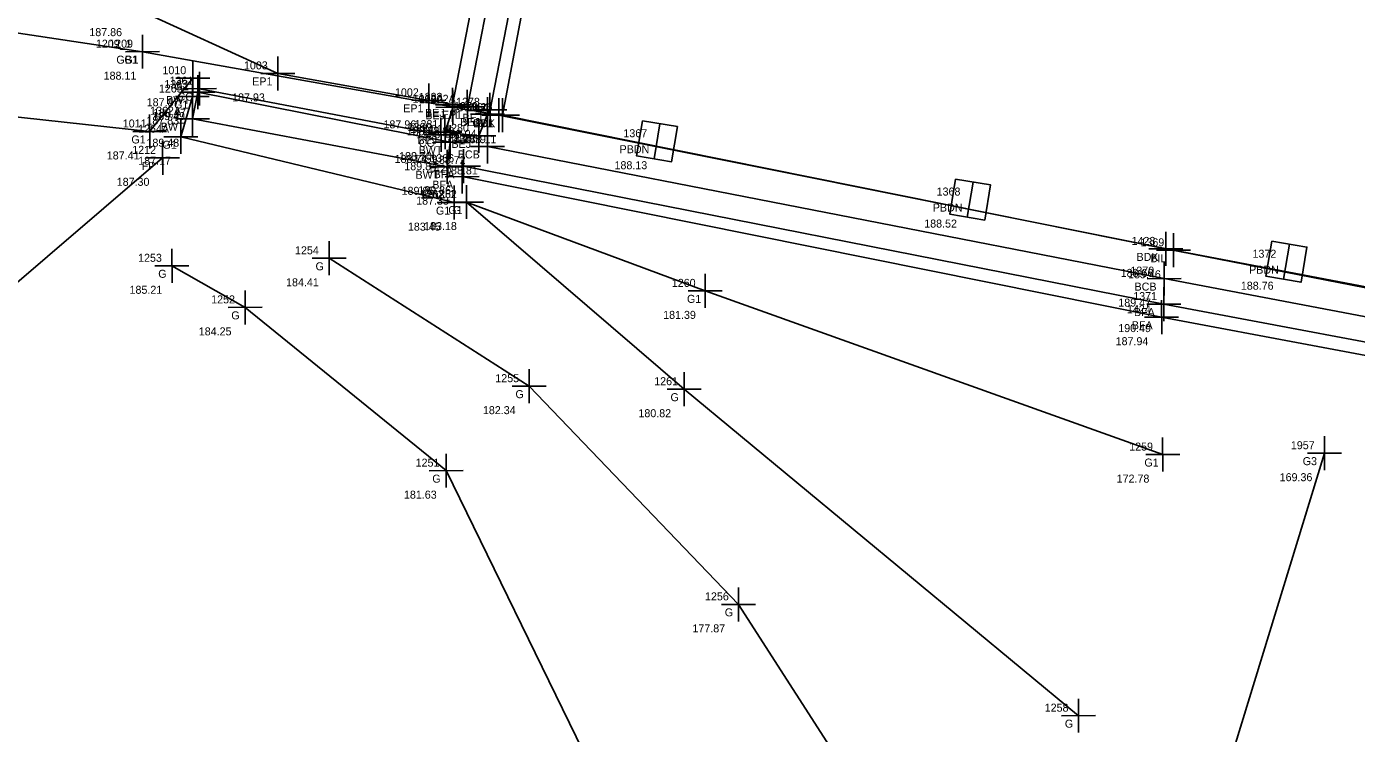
# Model space of a CAD drawing. Extents: x 1157913 to 1159198, y 600595 to 601244.
# Drawn here: x 1158460.89 to 1158510.75, y 600902.06 to 600928.57 of the extents above; entities that cross this region are included whole.
import ezdxf

# ---------------------------------------------------------------- set-up
doc = ezdxf.new("R2010")
doc.units = 0
for name, color, linetype in [('Default', 7, 'Continuous'), ('S_Bridge_Curb', 7, 'Continuous'), ('S_Bridge_Deck', 7, 'Continuous'), ('S_Bridge_Downspout', 7, 'Continuous'), ('S_Bridge_ExpansionJoint', 7, 'Continuous'), ('S_Bridge_Fascia', 7, 'Continuous'), ('S_Bridge_Rail', 7, 'Continuous'), ('S_Bridge_Wingwall', 7, 'Continuous'), ('S_Curb_Type_2', 7, 'Continuous'), ('S_Fencing_Page', 7, 'Continuous'), ('S_Field_Code', 7, 'Continuous'), ('S_Ground_Elevation', 7, 'Continuous'), ('S_Ground_LevelString', 7, 'Continuous'), ('S_Guardrail_Beam', 7, 'Continuous'), ('S_Point_Elevation', 7, 'Continuous'), ('S_Point_Name', 7, 'Continuous'), ('S_Roadway_Edge_Pavement', 7, 'Continuous'), ('S_Survey_Shot', 7, 'Continuous')]:
    doc.layers.add(name, color=color, linetype=linetype)

msp = doc.modelspace()

# ---------------------------------------------------------------- linework, layer by layer
at = {"layer": 'Default'}
for p, q in [((1158484.527, 600924.267), (1158484.527, 600924.267)), ((1158496.27, 600922.079), (1158496.27, 600922.079)), ((1158508.13, 600919.748), (1158508.13, 600919.748))]:
    msp.add_line(p, q, dxfattribs=at)
at = {"layer": 'S_Bridge_Curb'}
msp.add_lwpolyline([(1158478.174, 600924.072), (1158503.549, 600919.114), (1158527.549, 600914.557), (1158551.032, 600910.063), (1158574.638, 600905.207), (1158597.984, 600900.814), (1158621.679, 600896.121), (1158645.574, 600891.298), (1158668.721, 600886.601), (1158692.515, 600882.046), (1158718.247, 600876.909)], dxfattribs=at)
at = {"layer": 'S_Bridge_Deck'}
msp.add_lwpolyline([(1158483.154, 600948.642), (1158508.91, 600943.661), (1158532.625, 600939.025), (1158556.015, 600934.45), (1158579.602, 600929.788), (1158603.216, 600925.172), (1158626.871, 600920.52), (1158650.274, 600915.846), (1158673.938, 600911.396), (1158697.587, 600906.778), (1158722.887, 600901.626), (1158720.511, 600890.631), (1158717.86, 600878.361), (1158692.562, 600883.367), (1158669.405, 600887.913), (1158645.122, 600892.525), (1158622.108, 600897.299), (1158598.216, 600901.842), (1158574.819, 600906.519), (1158551.011, 600911.144), (1158527.523, 600915.567), (1158503.608, 600920.228), (1158478.738, 600925.244), (1158480.987, 600937.158)], close=True, dxfattribs=at)
at = {"layer": 'S_Bridge_Downspout'}
for p, q in [((1158484.637, 600924.924), (1158484.417, 600923.609)), ((1158496.38, 600922.737), (1158496.16, 600921.422)), ((1158508.24, 600920.405), (1158508.02, 600919.09))]:
    msp.add_line(p, q, dxfattribs=at)
for points in [[(1158483.979, 600925.034), (1158485.294, 600924.815), (1158485.075, 600923.5), (1158483.76, 600923.719)], [(1158495.722, 600922.847), (1158497.037, 600922.627), (1158496.817, 600921.312), (1158495.502, 600921.532)], [(1158507.583, 600920.515), (1158508.898, 600920.295), (1158508.678, 600918.98), (1158507.363, 600919.2)]]:
    msp.add_lwpolyline(points, close=True, dxfattribs=at)
at = {"layer": 'S_Bridge_ExpansionJoint'}
msp.add_lwpolyline([(1158482.951, 600950.133), (1158482.722, 600948.965), (1158482.812, 600948.797), (1158478.267, 600925.445), (1158478.173, 600925.283), (1158477.852, 600924.467), (1158476.579, 600924.608), (1158476.87, 600925.538), (1158476.863, 600925.631), (1158481.393, 600949.008), (1158481.599, 600948.931), (1158481.661, 600950.428)], close=True, dxfattribs=at)
at = {"layer": 'S_Bridge_Fascia'}
msp.add_lwpolyline([(1158477.27, 600923.329), (1158503.529, 600918.158), (1158527.207, 600913.702), (1158550.741, 600909.047), (1158574.385, 600904.349), (1158597.753, 600899.594), (1158621.448, 600895.033), (1158645.16, 600890.284), (1158668.539, 600885.727), (1158692.378, 600881.174), (1158718.73, 600875.851), (1158718.692, 600875.535), (1158691.877, 600880.706), (1158668.575, 600885.39), (1158645.229, 600889.981), (1158621.38, 600894.578), (1158597.772, 600899.255), (1158574.312, 600903.82), (1158550.668, 600908.561), (1158526.887, 600913.271), (1158503.449, 600917.667), (1158477.221, 600922.938)], close=True, dxfattribs=at)
at = {"layer": 'S_Bridge_Rail'}
msp.add_lwpolyline([(1158478.595, 600925.242), (1158503.898, 600920.176), (1158527.611, 600915.661), (1158551.296, 600911.071), (1158574.9, 600906.289), (1158598.35, 600901.85), (1158621.733, 600897.102), (1158645.532, 600892.49), (1158669.112, 600887.777), (1158692.742, 600883.154), (1158718.452, 600878.194)], dxfattribs=at)
at = {"layer": 'S_Bridge_Wingwall'}
msp.add_lwpolyline([(1158476.776, 600924.229), (1158476.659, 600923.307), (1158467.107, 600925.111), (1158467.311, 600926.11)], close=True, dxfattribs=at)
at = {"layer": 'S_Curb_Type_2'}
msp.add_lwpolyline([(1158476.428, 600924.505), (1158467.378, 600926.237)], dxfattribs=at)
at = {"layer": 'S_Fencing_Page'}
msp.add_lwpolyline([(1158465.992, 600923.644), (1158459.458, 600918.051), (1158430.263, 600900.283), (1158423.649, 600880.753)], dxfattribs=at)
at = {"layer": 'S_Ground_Elevation'}
for points in [[(1158251.54, 600967.593), (1158270.913, 600964.558), (1158289.206, 600961.108), (1158301.325, 600958.377), (1158322.741, 600954.164), (1158365.691, 600945.458), (1158419.19, 600936.361), (1158444.636, 600930.739), (1158465.241, 600927.625)], [(1158467.12, 600926.63), (1158465.505, 600924.633), (1158454.971, 600925.781), (1158437.209, 600926.67), (1158392.406, 600937.035), (1158351.859, 600945.261), (1158302.444, 600956.091), (1158278.739, 600959.765), (1158266.149, 600961.045), (1158251.992, 600960.565), (1158239.233, 600960.758)], [(1158503.489, 600912.514), (1158486.337, 600918.654), (1158477.388, 600921.986), (1158476.924, 600921.964), (1158466.672, 600924.435), (1158467.106, 600925.943)], [(1158500.336, 600902.721), (1158485.55, 600914.966), (1158477.388, 600921.986)], [(1158485.328, 600887.991), (1158481.758, 600901.391), (1158476.618, 600911.911), (1158469.082, 600918.035), (1158466.342, 600919.595)], [(1158472.24, 600919.876), (1158479.736, 600915.08), (1158487.585, 600906.896), (1158494.065, 600896.807)], [(1158417.202, 600659.944), (1158425.519, 600653.573), (1158433.344, 600650.427), (1158437.71, 600654.503), (1158444.811, 600658.736), (1158451.283, 600687.753), (1158462.34, 600743.775), (1158474.252, 600798.648), (1158489.994, 600853.766), (1158493.281, 600877.741), (1158501.025, 600884.706), (1158509.554, 600912.566)]]:
    msp.add_lwpolyline(points, dxfattribs=at)
at = {"layer": 'S_Ground_LevelString'}
msp.add_line((1158477.417, 600925.559), (1158477.417, 600925.559), dxfattribs=at)
msp.add_lwpolyline([(1158477.417, 600925.559), (1158479.75, 600937.525)], dxfattribs=at)
at = {"layer": 'S_Guardrail_Beam'}
msp.add_lwpolyline([(1158478.595, 600925.242), (1158465.241, 600927.625), (1158444.636, 600930.739), (1158419.355, 600935.124), (1158365.691, 600945.458), (1158322.741, 600954.164), (1158301.325, 600958.377), (1158291.145, 600959.788), (1158282.089, 600960.622), (1158269.189, 600961.294)], dxfattribs=at)
at = {"layer": 'S_Roadway_Edge_Pavement'}
msp.add_lwpolyline([(1158477.417, 600925.559), (1158475.969, 600925.8), (1158470.307, 600926.811), (1158464.953, 600929.258), (1158434.419, 600935.565), (1158394.467, 600943.733), (1158353.382, 600952.235), (1158303.702, 600962.318), (1158261.836, 600970.726), (1158252.612, 600972.631), (1158210.037, 600978.929), (1158172.668, 600988.59), (1158138.81, 600995.015), (1158098.517, 601002.533), (1158056.874, 601010.931), (1158005.398, 601020.726), (1157975.101, 601026.613), (1157952.322, 601030.415), (1157945.74, 601032.454), (1157914.88, 601038.54)], dxfattribs=at)
at = {"layer": 'S_Survey_Shot'}
for p, q in [((1158465.242, 600926.989), (1158465.24, 600928.262)), ((1158465.242, 600926.989), (1158465.24, 600928.262)), ((1158464.605, 600927.624), (1158465.877, 600927.627)), ((1158464.605, 600927.624), (1158465.877, 600927.627)), ((1158465.241, 600927.625), (1158465.241, 600927.625)), ((1158465.241, 600927.625), (1158465.241, 600927.625)), ((1158470.308, 600926.174), (1158470.305, 600927.447)), ((1158467.122, 600925.993), (1158467.119, 600927.266)), ((1158466.484, 600926.628), (1158467.757, 600926.631)), ((1158467.108, 600925.307), (1158467.105, 600926.579)), ((1158467.12, 600926.63), (1158467.12, 600926.63)), ((1158467.312, 600925.474), (1158467.309, 600926.747)), ((1158467.379, 600925.601), (1158467.377, 600926.874)), ((1158469.671, 600926.809), (1158470.943, 600926.812)), ((1158470.307, 600926.811), (1158470.307, 600926.811)), ((1158475.97, 600925.164), (1158475.967, 600926.436)), ((1158466.47, 600925.942), (1158467.742, 600925.944)), ((1158466.675, 600926.109), (1158467.947, 600926.112)), ((1158466.742, 600926.236), (1158468.014, 600926.239)), ((1158467.106, 600925.943), (1158467.106, 600925.943)), ((1158467.311, 600926.11), (1158467.311, 600926.11)), ((1158467.378, 600926.237), (1158467.378, 600926.237)), ((1158476.864, 600924.995), (1158476.862, 600926.267)), ((1158476.871, 600924.902), (1158476.868, 600926.174)), ((1158477.418, 600924.922), (1158477.415, 600926.195)), ((1158477.418, 600924.922), (1158477.415, 600926.195)), ((1158478.174, 600924.647), (1158478.171, 600925.919)), ((1158478.268, 600924.809), (1158478.265, 600926.081)), ((1158467.109, 600924.474), (1158467.106, 600925.747)), ((1158475.332, 600925.799), (1158476.605, 600925.801)), ((1158475.969, 600925.8), (1158475.969, 600925.8)), ((1158476.227, 600925.63), (1158477.499, 600925.632)), ((1158476.233, 600925.536), (1158477.506, 600925.539)), ((1158476.78, 600925.557), (1158478.053, 600925.56)), ((1158476.78, 600925.557), (1158478.053, 600925.56)), ((1158476.863, 600925.631), (1158476.863, 600925.631)), ((1158476.87, 600925.538), (1158476.87, 600925.538)), ((1158477.417, 600925.559), (1158477.417, 600925.559)), ((1158477.417, 600925.559), (1158477.417, 600925.559)), ((1158477.63, 600925.444), (1158478.903, 600925.446)), ((1158478.267, 600925.445), (1158478.267, 600925.445)), ((1158478.596, 600924.605), (1158478.594, 600925.878)), ((1158478.596, 600924.605), (1158478.594, 600925.878)), ((1158478.739, 600924.608), (1158478.736, 600925.88)), ((1158465.507, 600923.997), (1158465.504, 600925.27)), ((1158466.471, 600925.109), (1158467.743, 600925.112)), ((1158466.673, 600923.799), (1158466.671, 600925.071)), ((1158467.107, 600925.111), (1158467.107, 600925.111)), ((1158476.429, 600923.869), (1158476.427, 600925.141)), ((1158476.58, 600923.972), (1158476.577, 600925.245)), ((1158477.536, 600925.282), (1158478.809, 600925.285)), ((1158477.853, 600923.831), (1158477.85, 600925.104)), ((1158477.959, 600925.24), (1158479.231, 600925.243)), ((1158477.959, 600925.24), (1158479.231, 600925.243)), ((1158478.101, 600925.243), (1158479.374, 600925.245)), ((1158478.173, 600925.283), (1158478.173, 600925.283)), ((1158478.595, 600925.242), (1158478.595, 600925.242)), ((1158478.595, 600925.242), (1158478.595, 600925.242)), ((1158478.738, 600925.244), (1158478.738, 600925.244)), ((1158464.869, 600924.632), (1158466.142, 600924.635)), ((1158465.505, 600924.633), (1158465.505, 600924.633)), ((1158466.036, 600924.434), (1158467.308, 600924.436)), ((1158466.672, 600924.435), (1158466.672, 600924.435)), ((1158475.792, 600924.504), (1158477.064, 600924.506)), ((1158475.943, 600924.607), (1158477.215, 600924.61)), ((1158476.428, 600924.505), (1158476.428, 600924.505)), ((1158476.579, 600924.608), (1158476.579, 600924.608)), ((1158476.778, 600923.593), (1158476.775, 600924.866)), ((1158477.215, 600924.466), (1158478.488, 600924.469)), ((1158477.852, 600924.467), (1158477.852, 600924.467)), ((1158478.176, 600923.436), (1158478.173, 600924.708)), ((1158465.994, 600923.007), (1158465.991, 600924.28)), ((1158476.14, 600924.228), (1158477.412, 600924.231)), ((1158476.661, 600922.671), (1158476.658, 600923.943)), ((1158476.776, 600924.229), (1158476.776, 600924.229)), ((1158477.271, 600922.692), (1158477.269, 600923.965)), ((1158477.538, 600924.071), (1158478.811, 600924.073)), ((1158478.174, 600924.072), (1158478.174, 600924.072)), ((1158465.356, 600923.642), (1158466.628, 600923.645)), ((1158465.992, 600923.644), (1158465.992, 600923.644)), ((1158477.222, 600922.302), (1158477.22, 600923.574)), ((1158476.023, 600923.305), (1158477.296, 600923.308)), ((1158476.585, 600922.937), (1158477.857, 600922.939)), ((1158476.634, 600923.327), (1158477.906, 600923.33)), ((1158476.659, 600923.307), (1158476.659, 600923.307)), ((1158477.221, 600922.938), (1158477.221, 600922.938)), ((1158477.27, 600923.329), (1158477.27, 600923.329)), ((1158476.925, 600921.328), (1158476.922, 600922.601)), ((1158477.389, 600921.35), (1158477.386, 600922.622)), ((1158477.389, 600921.35), (1158477.386, 600922.622)), ((1158476.287, 600921.963), (1158477.56, 600921.966)), ((1158476.751, 600921.985), (1158478.024, 600921.987)), ((1158476.751, 600921.985), (1158478.024, 600921.987)), ((1158476.924, 600921.964), (1158476.924, 600921.964)), ((1158477.388, 600921.986), (1158477.388, 600921.986)), ((1158477.388, 600921.986), (1158477.388, 600921.986)), ((1158472.241, 600919.24), (1158472.238, 600920.513)), ((1158503.61, 600919.592), (1158503.607, 600920.865)), ((1158503.9, 600919.54), (1158503.897, 600920.813)), ((1158466.343, 600918.959), (1158466.34, 600920.231)), ((1158502.972, 600920.227), (1158504.245, 600920.23)), ((1158503.262, 600920.175), (1158504.535, 600920.178)), ((1158503.608, 600920.228), (1158503.608, 600920.228)), ((1158503.898, 600920.176), (1158503.898, 600920.176)), ((1158465.705, 600919.594), (1158466.978, 600919.597)), ((1158466.342, 600919.595), (1158466.342, 600919.595)), ((1158471.603, 600919.875), (1158472.876, 600919.878)), ((1158472.24, 600919.876), (1158472.24, 600919.876)), ((1158503.55, 600918.478), (1158503.548, 600919.75)), ((1158486.339, 600918.018), (1158486.336, 600919.29)), ((1158502.913, 600919.112), (1158504.185, 600919.115)), ((1158503.549, 600919.114), (1158503.549, 600919.114)), ((1158469.084, 600917.399), (1158469.081, 600918.672)), ((1158485.701, 600918.653), (1158486.973, 600918.655)), ((1158486.337, 600918.654), (1158486.337, 600918.654)), ((1158503.53, 600917.522), (1158503.528, 600918.794)), ((1158468.446, 600918.034), (1158469.718, 600918.037)), ((1158469.082, 600918.035), (1158469.082, 600918.035)), ((1158502.893, 600918.157), (1158504.165, 600918.159)), ((1158503.451, 600917.031), (1158503.448, 600918.303)), ((1158503.529, 600918.158), (1158503.529, 600918.158)), ((1158502.813, 600917.666), (1158504.085, 600917.668)), ((1158503.449, 600917.667), (1158503.449, 600917.667)), ((1158479.737, 600914.444), (1158479.734, 600915.716)), ((1158485.551, 600914.329), (1158485.549, 600915.602)), ((1158479.1, 600915.079), (1158480.372, 600915.081)), ((1158479.736, 600915.08), (1158479.736, 600915.08)), ((1158484.914, 600914.964), (1158486.186, 600914.967)), ((1158485.55, 600914.966), (1158485.55, 600914.966)), ((1158503.491, 600911.878), (1158503.488, 600913.15)), ((1158509.555, 600911.93), (1158509.552, 600913.203)), ((1158476.619, 600911.275), (1158476.617, 600912.547)), ((1158502.853, 600912.513), (1158504.126, 600912.516)), ((1158503.489, 600912.514), (1158503.489, 600912.514)), ((1158508.917, 600912.565), (1158510.19, 600912.568)), ((1158509.554, 600912.566), (1158509.554, 600912.566)), ((1158475.982, 600911.909), (1158477.254, 600911.912)), ((1158476.618, 600911.911), (1158476.618, 600911.911)), ((1158487.586, 600906.259), (1158487.584, 600907.532)), ((1158486.949, 600906.894), (1158488.221, 600906.897)), ((1158487.585, 600906.896), (1158487.585, 600906.896)), ((1158500.338, 600902.085), (1158500.335, 600903.357)), ((1158499.7, 600902.72), (1158500.973, 600902.722)), ((1158500.336, 600902.721), (1158500.336, 600902.721))]:
    msp.add_line(p, q, dxfattribs=at)

# ---------------------------------------------------------------- texts
at = {"layer": 'S_Field_Code'}
for s, p in [('GB1', (1158464.256, 600927.175)), ('G1', (1158464.556, 600927.175)), ('G1', (1158466.436, 600926.18)), ('EP1', (1158469.35, 600926.361)), ('BWT', (1158466.125, 600925.66)), ('CC', (1158466.549, 600925.787)), ('G1', (1158466.421, 600925.493)), ('EP1', (1158475.012, 600925.35)), ('BEJ', (1158475.833, 600925.181)), ('BWT', (1158465.921, 600924.661)), ('BEJ', (1158475.84, 600925.088)), ('EP1', (1158476.46, 600925.109)), ('L', (1158476.944, 600925.109)), ('BEJ', (1158477.143, 600924.833)), ('BEJ', (1158477.237, 600924.995)), ('GB1', (1158477.61, 600924.792)), ('BDK', (1158477.637, 600924.794)), ('BIL', (1158477.724, 600924.792)), ('G1', (1158464.82, 600924.183)), ('BEJ', (1158475.549, 600924.158)), ('G1', (1158465.987, 600923.985)), ('CC', (1158475.599, 600924.055)), ('BWT', (1158475.59, 600923.779)), ('BEJ', (1158476.822, 600924.017)), ('BCB', (1158477.059, 600923.622)), ('PBDN', (1158483.126, 600923.817)), ('FP', (1158465.206, 600923.194)), ('BWT', (1158475.474, 600922.857)), ('BFA', (1158476.153, 600922.879)), ('BFA', (1158476.104, 600922.488)), ('PBDN', (1158494.869, 600921.629)), ('G1', (1158476.239, 600921.514)), ('G1', (1158476.703, 600921.536)), ('G', (1158476.873, 600921.536)), ('BDK', (1158502.508, 600919.778)), ('BIL', (1158503.027, 600919.726)), ('G', (1158465.827, 600919.145)), ('G', (1158471.725, 600919.426)), ('PBDN', (1158506.73, 600919.298)), ('BCB', (1158502.434, 600918.664)), ('G1', (1158485.652, 600918.204)), ('BFA', (1158502.412, 600917.708)), ('G', (1158468.567, 600917.585)), ('BFA', (1158502.332, 600917.217)), ('G', (1158479.221, 600914.63)), ('G', (1158485.035, 600914.516)), ('G1', (1158502.804, 600912.064)), ('G3', (1158508.739, 600912.117)), ('G', (1158476.103, 600911.461)), ('G', (1158487.07, 600906.446)), ('G', (1158499.821, 600902.271))]:
    msp.add_text(s, height=0.3, dxfattribs=at).set_placement(p)
at = {"layer": 'S_Point_Elevation'}
for s, p in [('187.86', (1158463.243, 600928.208)), ('188.11', (1158463.779, 600926.575)), ('188.11', (1158463.779, 600926.575)), ('187.93', (1158468.597, 600925.761)), ('187.87', (1158465.394, 600925.58)), ('188.47', (1158465.64, 600925.187)), ('187.83', (1158465.382, 600924.893)), ('189.49', (1158465.603, 600925.06)), ('187.96', (1158474.273, 600924.75)), ('188.73', (1158475.145, 600924.488)), ('188.01', (1158475.273, 600924.581)), ('188.00', (1158475.7, 600924.509)), ('188.00', (1158475.7, 600924.509)), ('188.79', (1158476.463, 600924.233)), ('188.04', (1158476.533, 600924.395)), ('188.79', (1158476.885, 600924.192)), ('188.79', (1158476.885, 600924.192)), ('188.11', (1158477.276, 600924.194)), ('189.48', (1158465.385, 600924.061)), ('187.41', (1158463.897, 600923.583)), ('187.17', (1158465.075, 600923.385)), ('188.74', (1158474.69, 600923.455)), ('188.70', (1158474.857, 600923.558)), ('189.84', (1158475.054, 600923.179)), ('188.72', (1158476.127, 600923.417)), ('188.13', (1158482.935, 600923.217)), ('188.81', (1158476.582, 600923.022)), ('187.30', (1158464.27, 600922.594)), ('189.85', (1158474.952, 600922.257)), ('189.86', (1158475.576, 600922.279)), ('187.33', (1158475.497, 600921.888)), ('183.45', (1158475.188, 600920.914)), ('183.18', (1158475.796, 600920.936)), ('183.18', (1158475.796, 600920.936)), ('188.52', (1158494.548, 600921.029)), ('188.66', (1158501.915, 600919.178)), ('189.46', (1158502.191, 600919.126)), ('184.41', (1158470.619, 600918.826)), ('188.76', (1158506.42, 600918.698)), ('185.21', (1158464.75, 600918.545)), ('189.47', (1158501.825, 600918.064)), ('181.39', (1158484.759, 600917.604)), ('184.25', (1158467.346, 600916.985)), ('190.49', (1158501.824, 600917.108)), ('187.94', (1158501.725, 600916.617)), ('182.34', (1158478, 600914.03)), ('180.82', (1158483.831, 600913.916)), ('172.78', (1158501.763, 600911.464)), ('169.36', (1158507.875, 600911.516)), ('181.63', (1158475.04, 600910.861)), ('177.87', (1158485.856, 600905.846))]:
    msp.add_text(s, height=0.3, dxfattribs=at).set_placement(p)
at = {"layer": 'S_Point_Name'}
for s, p in [('1209_1', (1158463.488, 600927.775)), ('1209', (1158463.987, 600927.775)), ('1010', (1158465.984, 600926.78)), ('1003', (1158469.041, 600926.961)), ('1363', (1158466.054, 600926.26)), ('1361', (1158466.251, 600926.387)), ('1265', (1158465.85, 600926.093)), ('1002', (1158474.703, 600925.95)), ('1002A_1', (1158475.367, 600925.709)), ('1283', (1158475.592, 600925.781)), ('1282', (1158475.599, 600925.688)), ('1002A', (1158475.82, 600925.709)), ('1362A', (1158465.52, 600925.261)), ('1364_1', (1158476.826, 600925.392)), ('1279', (1158476.914, 600925.433)), ('1278', (1158476.994, 600925.595)), ('1364', (1158477.324, 600925.392)), ('1426', (1158477.467, 600925.394)), ('1011', (1158464.497, 600924.783)), ('1360', (1158475.174, 600924.655)), ('1281', (1158475.438, 600924.758)), ('1280', (1158476.583, 600924.617)), ('1264A', (1158465.071, 600924.585)), ('1358', (1158475.505, 600924.379)), ('1365', (1158476.918, 600924.222)), ('1367', (1158483.268, 600924.417)), ('1212', (1158464.851, 600923.794)), ('1359', (1158475.403, 600923.457)), ('1366', (1158476.028, 600923.479)), ('1425', (1158475.936, 600923.088)), ('1262_1', (1158475.633, 600922.136)), ('1262', (1158476.131, 600922.136)), ('1368', (1158495.013, 600922.229)), ('1263', (1158475.667, 600922.114)), ('1423', (1158502.323, 600920.378)), ('1369', (1158502.656, 600920.326)), ('1253', (1158465.071, 600919.745)), ('1254', (1158470.955, 600920.026)), ('1372', (1158506.857, 600919.898)), ('1370', (1158502.278, 600919.264)), ('1260', (1158485.083, 600918.804)), ('1252', (1158467.811, 600918.185)), ('1371', (1158502.386, 600918.308)), ('1424', (1158502.15, 600917.817)), ('1255', (1158478.465, 600915.23)), ('1261', (1158484.423, 600915.116)), ('1259', (1158502.233, 600912.664)), ('1957', (1158508.295, 600912.716)), ('1251', (1158475.477, 600912.061)), ('1256', (1158486.328, 600907.046)), ('1258', (1158499.065, 600902.871))]:
    msp.add_text(s, height=0.3, dxfattribs=at).set_placement(p)

doc.saveas('drawing.dxf')
